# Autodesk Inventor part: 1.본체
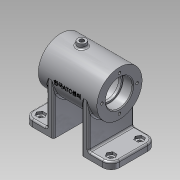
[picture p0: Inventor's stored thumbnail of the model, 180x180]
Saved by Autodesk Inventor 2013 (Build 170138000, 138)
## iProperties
Created: 2017-02
Part Number: 1.본체
Material: 알루미늄 6061
Document SubType Name: Modeling
Designer: hana-cad19
Density: 2.71 g/cm^3
Mass: 356.083 g
Surface Area: 422.772 cm^2
Volume: 131.396 cm^3
Author: hana-cad19
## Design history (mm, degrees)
sketch "스케치1"
  geometry: C1 r 27 at (0, 0); 1 further point
  constraints: 1 centre point, 1 coincident
  dimensions: "d0" = 54 diameter of C1
extrude "돌출1" new body sketch "스케치1" stored distance "d2" = 70; taper "d3" = 0 deg
node "작업 평면1"
sketch "스케치2"
  geometry: L1 (-27, 0)-(-27, -60); L2 (-27, -60)-(27, -60); L3 (27, -60)-(27, 0); A1 r 27 centre (0, 0) between (-27, 0) and (27, 0) reference; 1 further point
  constraints: 6 end point, 2 point on circle, 2 tangent, 1 parallel, 1 perpendicular, 1 vertical
  dimensions: "d5" = 60 distance from line of L2 L3.end
extrude "돌출2" join sketch "스케치2" distance "d7" = 8; taper "d8" = 0 deg
node "작업 평면2"
sketch "스케치3"
  geometry: L1 (25, -60)-(25, 0) reference; L2 (25, -60)-(52, -60); L3 (52, -60)-(52, -52); L4 (52, -52)-(25, -52); 1 further point
  constraints: 6 end point, 3 perpendicular, 1 point on line
  dimensions: "d10" = 8 distance between parallel lines of L4 L2; "d12" = 52 distance from line of L3 point (0, 0)
extrude "돌출3" join sketch "스케치3" stored distance "d13" = 54; taper "d14" = 0 deg
sketch "스케치4"
  geometry: L1 (-35, 27)-(-35, -27) reference; L2 (35, -27)-(35, 27) reference; L3 (-35, 0)-(35, 0); L4 (-35, 16)-(-23.3, 16); L5 (-23, 15.7)-(-23, 14); L6 (-23, 14)-(-20, 14); L7 (-20, 14)-(-20, 19); L8 (-17, 22)-(17, 22); L9 (20, 19)-(20, 14); L10 (20, 14)-(23, 14); L11 (23, 14)-(23, 15.7); L12 (23.3, 16)-(35, 16); A1 r 3 centre (-17, 19) between (-17, 22) and (-20, 19); A2 r 3 centre (17, 19) between (20, 19) and (17, 22); A3 r 0.3 centre (-23.3, 15.7) between (-23, 15.7) and (-23.3, 16); A4 r 0.3 centre (23.3, 15.7) between (23.3, 16) and (23, 15.7); 1 further point
  constraints: 20 end point, 9 parallel, 8 point on circle, 8 tangent, 4 centre point, 2 equal radius, 2 midpoint, 2 perpendicular, 2 point on line
  dimensions: "d15" = 12 distance between parallel lines of L5 L1; "d16" = 40 distance between parallel lines of L9 L7; "d17" = 12 distance between parallel lines of L2 L11; "d18" = 3 distance between parallel lines of L7 L5; "d19" = 28 diameter of L6 L3; "d20" = 32 diameter of L4 L3; "d21" = 44 diameter of L8 L3; "d22" = 3 radius of A1; "d23" = 0.3 radius of A3
revolve "회전1" sketch "스케치4" stored, may be unused: angle "d24" = 90 deg
sketch "스케치5"
  geometry: C1 r 16 at (0, 0) reference; 1 further point
  constraints: 1 horizontal alignment
  dimensions: "d25" = 21 distance of C1.centre point (-21, 0)
hole "구멍1" sketch "스케치5" at (-21, 0) diameter "d26" = 3.242; stored, may be unused: countersink angle "d30" = 90 deg, drill point angle "d32" = 118 deg; dims "d27" = 8, "d28" = 4, "d29" = 2, "d31" = 10
node "작업 평면3"
sketch "스케치6"
  geometry: L1 (-35, 27)-(-35, -27) reference; C1 r 5 at (-10, 0); 1 further point
  constraints: 1 centre point, 1 horizontal alignment
  dimensions: "d37" = 10 diameter of C1; "d39" = 25 distance from line of C1.centre L1
extrude "돌출4" join sketch "스케치6" stored distance "d40" = 54; taper "d41" = 0 deg
sketch "스케치7"
  geometry: C1 r 5 at (0, 0) reference; 1 further point
hole "구멍2" sketch "스케치7" at (0, 0) diameter "d42" = 5.188; stored, may be unused: countersink angle "d46" = 90 deg, drill point angle "d48" = 118 deg; dims "d43" = 8, "d44" = 4, "d45" = 2, "d47" = 10
sketch "스케치8"
  geometry: L1 (0, 0)-(0, -27); L2 (0, 0)-(16.339, -25.16); L3 (16.339, -25.16)-(11.307, -28.428); L4 (11.307, -28.428)-(8.039, -23.396); L5 (8.039, -23.396)-(13.071, -20.128); A1 r 27 centre (0, 0) between (-27, 0) and (27, 0) reference; 1 further point
  constraints: 10 end point, 3 perpendicular, 1 point on circle, 1 point on line
  dimensions: "d49" = 12 diameter of L4 L2; "d51" = 33 deg angle of L2 L1; "d53" = 30 distance of L2.end point (0, 0); "d54" = 6 distance between parallel lines of L3 L5
revolve "회전2" sketch "스케치8" stored, may be unused: angle "d55" = 90 deg
sketch "스케치9"
  geometry: C1 r 6 at (0, 0) reference
hole "구멍3" sketch "스케치9" at (0, 0) diameter "d56" = 5.188; stored, may be unused: countersink angle "d60" = 90 deg, drill point angle "d62" = 118 deg; dims "d57" = 8, "d58" = 4, "d59" = 2, "d61" = 10
chamfer "모따기1" distance "d63" = 1; stored, may be unused: second distance "d64" = 2, angle "d65" = 45 deg
sketch "스케치10" dims "d69" = 9
  geometry: L1 (-50, 0)-(-50, 54) reference; L2 (-77, 54)-(-50, 54) reference; L3 (-77, 0)-(-77, 54) reference; L4 (-50, 0)-(-77, 0) reference; L5 (-42, 0)-(-50, 0) reference; L6 (-42, 54)-(-42, 0) reference; L7 (-50, 54)-(-42, 54) reference; L8 (0, 54)-(0, 0) reference; L9 (27, 0)-(0, 0) reference; L10 (27, 54)-(27, 0) reference; L11 (0, 54)-(27, 54) reference; L12 (-8, 54)-(0, 54) reference; L13 (-8, 0)-(-8, 54) reference; L14 (0, 0)-(-8, 0) reference; L15 (-67, 10)-(17, 10); L16 (17, 10)-(17, 44); L17 (17, 44)-(-67, 44); L18 (-67, 44)-(-67, 10); L19 (-67, 10)-(17, 44); L20 (17, 10)-(-67, 44); L21 (14.402, 39.5)-(11.804, 44); L22 (11.804, 44)-(14.402, 48.5); L23 (14.402, 48.5)-(19.598, 48.5); L24 (19.598, 48.5)-(22.196, 44); L25 (22.196, 44)-(19.598, 39.5); L26 (19.598, 39.5)-(14.402, 39.5); 4 further points
  constraints: 24 end point, 3 midpoint, 2 coincident, 2 parallel, 1 horizontal, 1 horizontal alignment, 1 perpendicular, 1 vertical alignment, 15 other
  dimensions: "d66" = 84 distance between parallel lines of L16 L18; "d68" = 34 distance between parallel lines of L15 L17
extrude "돌출5" cut sketch "스케치10" distance "d70" = 3; taper "d71" = 0 deg
sketch "스케치11"
  geometry: L1 (14.402, 48.5)-(19.598, 48.5) reference; C1 r 2.5 at (17, 44); 3 further points
  constraints: 1 centre point, 1 horizontal alignment, 1 midpoint, 1 vertical alignment
  dimensions: "d72" = 5 diameter of C1
extrude "돌출6" cut sketch "스케치11" stored distance "d74" = 3; taper "d75" = 0 deg
fillet "모깎기1" dims "d76" = 10
fillet "모깎기2" dims "d77" = 2
fillet "모깎기3" dims "d78" = 2
fillet "모깎기4" dims "d79" = 2
fillet "모깎기5" dims "d80" = 2
fillet "모깎기6" dims "d81" = 2
fillet "모깎기7" dims "d82" = 2
node "작업 평면4"
sketch "스케치12"
  geometry: L1 (-35, 27)-(-35, -27) reference; L2 (-35, 27)-(35, 27) reference; 2 further points
  constraints: 1 other
  dimensions: "d84" = 35 distance from line of point (0, 0) L1; "d85" = 27 distance from line of L2 point (0, 0)
feature "엠보싱1" sketch "스케치12" dims "d86" = 0.5, "d87" = 0
node "솔리드1"
mirror "대칭1"
pattern_circular "원형 패턴1" dims angle "d34" = 360 deg
mirror "대칭2"
mirror "대칭3"
mirror "대칭4"
node "절단 모서리 투영1"
other parameters: "d4" = 17, "d9" = 90 deg, "d36" = 32
